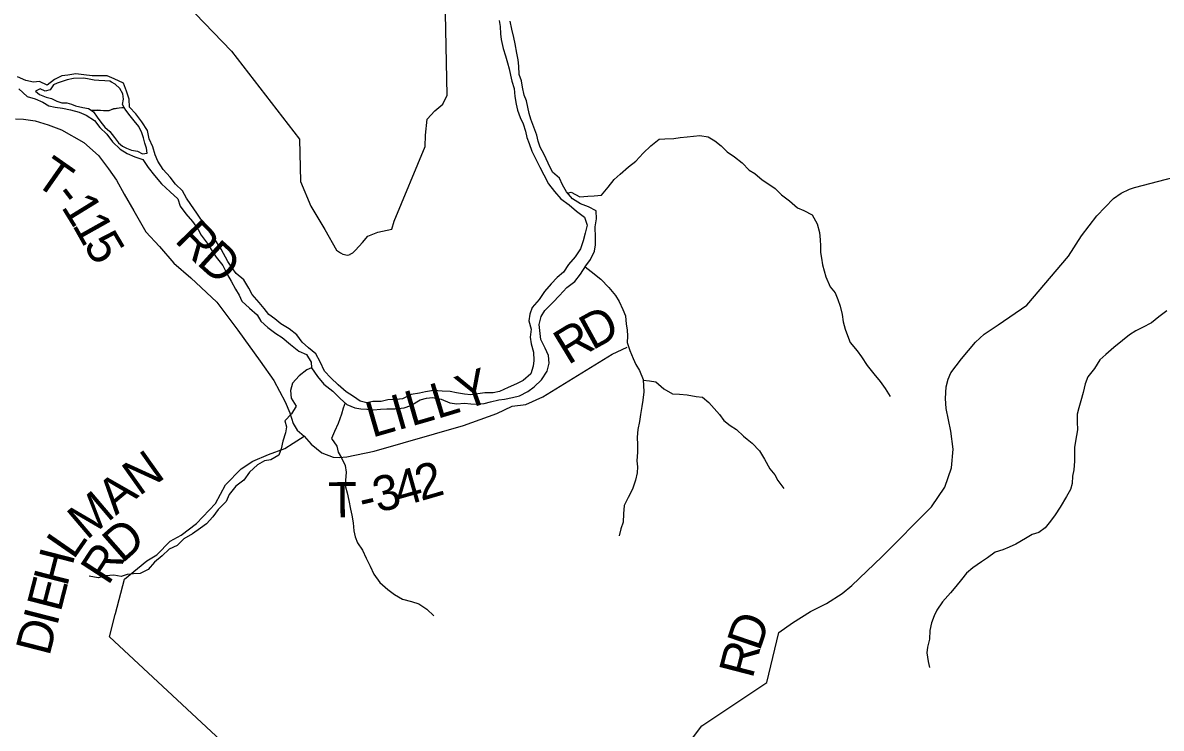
# Model space of a CAD drawing. Extents: x 1624196 to 2029251, y 146837 to 440034.
# Drawn here: x 1784289 to 1793997, y 302092 to 308107 of the extents above; entities that cross this region are included whole.
import ezdxf

# ---------------------------------------------------------------- set-up
doc = ezdxf.new("R2010")
doc.units = 0
for name, color, linetype in [('GM_X_County_Road', 7, 'Continuous'), ('GM_X_County_Road_Text', 7, 'Continuous'), ('GM_X_Minor_Lake', 7, 'Continuous'), ('GM_X_Minor_River', 7, 'Continuous'), ('GM_X_Township_Road', 7, 'Continuous'), ('GM_X_Township_Road_Text', 7, 'Continuous')]:
    doc.layers.add(name, color=color, linetype=linetype)

msp = doc.modelspace()

# ---------------------------------------------------------------- linework, layer by layer
at = {"layer": 'GM_X_County_Road'}
msp.add_lwpolyline([(1788583.9, 300127.8), (1790079.3, 302113.6), (1790633, 302481.1), (1790737.1, 302906.8), (1790852.9, 302990.4), (1791006.8, 303086.3), (1791142.9, 303154), (1791274.8, 303241.7), (1791358.6, 303308.8), (1791613.6, 303554.5), (1792037.8, 303980.6), (1792150.8, 304148.4), (1792209.5, 304311.7), (1792222, 304472.6), (1792202.5, 304625), (1792162.4, 304817.4), (1792156, 304902.5), (1792162.3, 305002.2), (1792180.9, 305067.6), (1792203.7, 305121.2), (1792293, 305242.6), (1792412.3, 305384.4), (1792486.3, 305450.9), (1792605.9, 305531), (1792849.6, 305698.2), (1793205.5, 306117.6), (1793316.5, 306289.4), (1793447.5, 306461.5), (1793590.9, 306607.6), (1793654.6, 306655.1), (1793726.3, 306689.4), (1793768.9, 306703.8), (1794314.5, 306843.9)], dxfattribs=at)
at = {"layer": 'GM_X_Minor_Lake'}
for points in [[(1785046.2, 307600.2), (1785032, 307608.1), (1784990.1, 307612.5), (1784938.1, 307614.9), (1784898.2, 307617.3), (1784856.2, 307625.6), (1784808.4, 307636), (1784720.4, 307632.8), (1784668.3, 307621.2), (1784624.2, 307605.5), (1784582.1, 307591.8), (1784552, 307578.1), (1784523.7, 307536.2), (1784479.6, 307524.6), (1784437.7, 307543), (1784397.6, 307523.2), (1784432.3, 307494.3)], [(1785153.3, 307385.4), (1785138.3, 307410.9), (1785146.7, 307454.9), (1785141.1, 307501.1), (1785115.4, 307545.3), (1785075.8, 307583.7), (1785046.2, 307600.2)], [(1784432.3, 307494.3), (1784489.1, 307472.4), (1784535, 307462), (1784580.8, 307437.6), (1784622.7, 307425.2), (1784664.6, 307424.9), (1784704.5, 307412.5), (1784738.4, 307400.2), (1784800.2, 307385.7), (1784848.2, 307377.3), (1784872.3, 307360.5)], [(1784872.3, 307360.5), (1784928, 307362.6), (1784977.9, 307358.2), (1785021.9, 307357.8), (1785062, 307373.5), (1785110.1, 307381.1), (1785153.3, 307385.4)], [(1784874.1, 307359.3), (1784891.9, 307346.9), (1784923.5, 307302.5), (1784955.1, 307260.2), (1784988.7, 307217.9), (1785030.4, 307179.5), (1785072, 307129), (1785105.6, 307082.7), (1785139.3, 307056.3), (1785173.1, 307038), (1785217, 307019.6), (1785266.9, 307011.2), (1785310.7, 306990.8), (1785350.7, 306994.5), (1785343.1, 307036.6), (1785329.4, 307080.8), (1785319.8, 307125), (1785304.2, 307169.2), (1785278.6, 307221.5), (1785239.1, 307269.9), (1785203.4, 307312.2), (1785167.9, 307360.6), (1785154.5, 307383.4)], [(1785154.5, 307383.4), (1785110.3, 307379.5), (1785062.5, 307371.9), (1785022.2, 307356.1), (1784977.9, 307356.5), (1784927.9, 307360.9), (1784874.1, 307359.3)]]:
    msp.add_lwpolyline(points, dxfattribs=at)
at = {"layer": 'GM_X_Minor_River'}
for points in [[(1788350.8, 308127.5), (1788360.4, 308075.4), (1788361.8, 308013.2), (1788367.4, 307963.1), (1788384.8, 307888.8), (1788406.2, 307824.6), (1788423.7, 307766.3), (1788435.3, 307714.1), (1788448.8, 307659.9), (1788460.4, 307607.8), (1788477.9, 307547.5), (1788485.3, 307479.3), (1788496.7, 307413.1), (1788506.3, 307363), (1788531.8, 307298.7), (1788555.3, 307244.4)], [(1788770.9, 305269.5), (1788743.3, 305333.9), (1788707.8, 305406.3), (1788702.1, 305456.5), (1788692.6, 305534.8), (1788709.1, 305602.9), (1788741.5, 305654.8), (1788808, 305720.6), (1788864.5, 305782.4), (1788927, 305850.2), (1788997.4, 305901.8), (1789043.9, 305963.7), (1789090.4, 306035.6), (1789130.8, 306087.5), (1789163.3, 306159.5), (1789173.7, 306213.6), (1789174.1, 306275.8), (1789168.7, 306366.1), (1789181.2, 306434.2), (1789177.6, 306502.4), (1789113.8, 306536.9), (1789045.9, 306563.4), (1788976.1, 306606), (1788924.5, 306664.5), (1788892.8, 306724.8), (1788865.2, 306781.2), (1788807.5, 306833.7), (1788767.9, 306910.2), (1788734.4, 306982.6), (1788700.8, 307047), (1788685.1, 307097.2), (1788671.4, 307149.5), (1788647.9, 307217.8), (1788620.3, 307284.2), (1788606.6, 307334.4), (1788594.9, 307388.6), (1788585.3, 307440.8), (1788563.6, 307491.1), (1788550, 307559.4), (1788542.4, 307611.6), (1788522.7, 307665.9), (1788519.2, 307736.1), (1788513.5, 307792.3), (1788501.9, 307848.5), (1788488.4, 307928.8), (1788476.8, 307981), (1788459.2, 308051.4), (1788445.7, 308119.6)], [(1785173.2, 307522.8), (1785147.8, 307591.2), (1785068.2, 307629.9), (1785008.4, 307654.4), (1784936.5, 307655), (1784880.5, 307653.5), (1784810.6, 307662.1), (1784740.7, 307672.7), (1784672.6, 307661.2), (1784622.6, 307653.6), (1784560.4, 307624.1), (1784496, 307574.5), (1784432.3, 307605.1), (1784380.2, 307599.5), (1784314.4, 307614.1), (1784244.7, 307644.7)], [(1784255.3, 307542.9), (1784326.9, 307478.3), (1784394.8, 307457.8), (1784458.7, 307429.3), (1784510.6, 307398.8), (1784564.5, 307386.5), (1784626.6, 307378.1), (1784696.5, 307363.6), (1784768.5, 307345), (1784830.4, 307320.6), (1784900.2, 307274), (1784945.8, 307213.5), (1785005.5, 307157), (1785055.1, 307090.5), (1785118.8, 307029.9), (1785178.6, 306993.4), (1785244.5, 306964.9), (1785312.4, 306940.4), (1785358, 306871.9), (1785411.6, 306805.4), (1785473.2, 306732.8), (1785546.8, 306666.1), (1785610.5, 306605.6), (1785632.1, 306543.2), (1785679.7, 306478.8), (1785735.3, 306412.2), (1785784.9, 306345.7), (1785810.6, 306295.4), (1785862.2, 306228.9), (1785901.8, 306164.5), (1785937.5, 306108.1), (1785995.1, 306037.5), (1786034.6, 305957), (1786066.2, 305902.7), (1786101.8, 305836.2), (1786133.5, 305783.9), (1786157.2, 305733.6), (1786222.9, 305673), (1786288.6, 305616.4), (1786320.3, 305564.1), (1786378, 305509.6), (1786447.7, 305457), (1786499.5, 305422.5), (1786571.2, 305363.9), (1786642.9, 305307.3), (1786708.8, 305278.8), (1786748.4, 305214.3), (1786752.1, 305164.2), (1786801.6, 305089.7), (1786857.2, 305025.1), (1786932.9, 304966.5), (1786996.6, 304903.9), (1787052.3, 304853.4), (1787120.2, 304822.9), (1787172.2, 304816.5), (1787222.2, 304812.2), (1787280.2, 304807.8), (1787338.3, 304813.4), (1787394.4, 304815.1), (1787464.5, 304816.6), (1787542.6, 304824.2), (1787598.8, 304843.9), (1787677.2, 304891.5), (1787731.4, 304905.2), (1787781.5, 304910.9), (1787857.5, 304898.3), (1787929.3, 304865.8), (1787991.3, 304857.4), (1788055.4, 304863), (1788109.5, 304858.6), (1788159.5, 304856.3), (1788223.6, 304859.9), (1788277.8, 304875.6), (1788348, 304893.2), (1788398.1, 304898.9), (1788464.2, 304912.5), (1788524.4, 304926.2), (1788596.7, 304963.8), (1788651, 305001.5), (1788711.5, 305063.3), (1788760, 305137.2), (1788776.5, 305203.3), (1788770.9, 305269.5)], [(1788555.3, 307244.4), (1788574.8, 307182.1), (1788588.3, 307127.9), (1788605.9, 307077.7), (1788631.3, 307013.4), (1788698.1, 306876.6), (1788731.5, 306810.2), (1788772.9, 306733.7), (1788824.3, 306669.2), (1788877.8, 306606.7), (1788947.3, 306554), (1789010.8, 306501.4), (1789078.4, 306450.8), (1789101.8, 306382.4), (1789085.2, 306312.5), (1789066.6, 306246.5), (1789046.1, 306180.6), (1788999.5, 306110.8), (1788943, 306045.2), (1788900.5, 305979.5), (1788846.1, 305935.8), (1788793.7, 305882.2), (1788737.2, 305816.5), (1788692.6, 305748.8), (1788634.1, 305679.2), (1788613.6, 305623.2), (1788605.1, 305565.2), (1788624.5, 305494.9), (1788616, 305426.9), (1788625.5, 305370.7), (1788644.9, 305298.5), (1788648.3, 305228.3), (1788641.8, 305178.3), (1788621.3, 305112.3), (1788554.9, 305056.8), (1788498.7, 305029.2), (1788428.4, 304995.8), (1788354.2, 304964.3), (1788300.1, 304952.7), (1788228.1, 304951.3), (1788168.1, 304943.8), (1788110, 304934.3), (1788056.1, 304940.7), (1787986.2, 304951.3), (1787934.4, 304961.8), (1787864.4, 304966.4), (1787792.5, 304971), (1787724.4, 304959.5), (1787672.4, 304947.9), (1787602.3, 304936.5), (1787528, 304901), (1787476, 304893.5), (1787402, 304892.1), (1787345.9, 304876.5), (1787274, 304877.1), (1787221.9, 304865.5), (1787166.1, 304882), (1787110.4, 304920.5), (1787046.8, 304959.1), (1786977.3, 305019.8), (1786915.8, 305078.4), (1786862.3, 305136.9), (1786825, 305215.4), (1786787.6, 305283.8), (1786726.1, 305334.4), (1786670.5, 305382.9), (1786627.1, 305447.4), (1786559.5, 305498), (1786489.9, 305538.7), (1786438.3, 305583.2), (1786386.6, 305619.7), (1786347.1, 305670.1), (1786305.5, 305720.5), (1786246.1, 305791.1), (1786216.6, 305843.4), (1786175.2, 305913.9), (1786107.7, 305970.5), (1786072.2, 306020.9), (1786038.6, 306071.3), (1785979.5, 306175.9), (1785934.1, 306246.4), (1785890.7, 306312.9), (1785867.2, 306369.2), (1785807.8, 306433.8), (1785772.2, 306484.2), (1785720.9, 306558.7), (1785685.3, 306611.1), (1785651.9, 306673.5), (1785590.4, 306730.1), (1785546.9, 306790.5), (1785487.5, 306857.1), (1785442.1, 306925.6), (1785418.5, 306979.9), (1785399.1, 307048.2), (1785367.7, 307116.6), (1785352.3, 307188.8), (1785305, 307261.3), (1785253.6, 307331.9), (1785198.1, 307388.4), (1785196.6, 307454.5), (1785173.2, 307522.8)], [(1788932.7, 306655.1), (1788966.5, 306662.2), (1789040.3, 306621.6), (1789106.4, 306629.2), (1789160.5, 306630.9), (1789222.6, 306638.5), (1789281.1, 306706.3), (1789331.6, 306770.1), (1789384, 306816), (1789454.5, 306879.7), (1789516.8, 306927.4), (1789579.4, 306995.2), (1789643.9, 307059), (1789714.3, 307114.7), (1789764.4, 307116.3), (1789840.5, 307119.9), (1789894.6, 307127.5), (1789954.7, 307135.2), (1790008.8, 307140.8), (1790062.9, 307144.5), (1790132.9, 307134), (1790190.7, 307099.6), (1790244.5, 307059.1), (1790294.2, 307006.6), (1790358, 306964.1), (1790423.7, 306911.5), (1790482, 306849.3)], [(1790482, 306849.3), (1790530.8, 306821), (1790594.7, 306768.4), (1790650.7, 306731.9), (1790704.6, 306693.5), (1790758.4, 306641), (1790828.4, 306588.4), (1790896.2, 306529.8), (1790948.3, 306507.4), (1791020.3, 306468.8), (1791063.9, 306392.3), (1791081.5, 306317.9), (1791089.1, 306255.7), (1791092.8, 306205.5), (1791092.4, 306149.3), (1791100.1, 306099.1), (1791109.8, 306042.8), (1791123.5, 305990.6), (1791137.2, 305940.3), (1791174.8, 305855.8), (1791216.6, 305803.4), (1791238.3, 305747), (1791258, 305690.7), (1791275.6, 305620.4), (1791285.3, 305558.1), (1791302.9, 305493.8), (1791322.6, 305441.5), (1791344.3, 305381.2), (1791404.1, 305308.6), (1791441.9, 305258.1), (1791489.6, 305185.6), (1791547.3, 305113), (1791599.1, 305048.5), (1791642.8, 304988), (1791684.5, 304919.5)], [(1789083.4, 306024.8), (1789136.1, 305987.2), (1789217.8, 305920.5), (1789285.4, 305849.9), (1789343, 305781.3), (1789374.7, 305731), (1789406.3, 305662.5), (1789427.9, 305608.3), (1789435.5, 305538), (1789443.1, 305487.8), (1789444.8, 305435.7), (1789442.4, 305381.5), (1789466, 305313.2), (1789493.6, 305244.8), (1789517.2, 305192.5), (1789548.9, 305142.2), (1789578.5, 305065.8), (1789585.8, 304961.4), (1789577.3, 304889.3), (1789566.9, 304835.2), (1789556.4, 304767.1), (1789548, 304707), (1789533.6, 304638.9), (1789529.1, 304574.7), (1789530.7, 304508.5), (1789532.2, 304446.3), (1789525.7, 304372.2), (1789531.4, 304320), (1789529.1, 304269.9), (1789512.6, 304207.8), (1789488.1, 304129.7), (1789451.6, 304059.8), (1789417.1, 303991.8), (1789412.6, 303919.6), (1789410.1, 303847.5), (1789389.7, 303793.4), (1789375.3, 303731.4)], [(1794043.7, 305652), (1793975.1, 305600.2), (1793914.6, 305548.4), (1793836, 305508.7), (1793781.7, 305480.9), (1793725.2, 305445.1), (1793666.7, 305397.3), (1793592.1, 305339.6), (1793525.4, 305277.8), (1793472.9, 305231.9), (1793428.3, 305160), (1793371.6, 305088), (1793349.2, 305028), (1793330.6, 304953.8), (1793310.1, 304883.7), (1793293.6, 304823.6), (1793281.2, 304769.5), (1793278.8, 304705.3), (1793282.4, 304637), (1793265.7, 304540.8), (1793257.3, 304484.7), (1793256.9, 304430.5), (1793258.5, 304370.3), (1793252, 304296.1), (1793241.6, 304239.9), (1793237.2, 304177.7), (1793222.8, 304127.7), (1793190.3, 304067.6), (1793135.5, 303977.7), (1793093, 303911.7), (1793052.5, 303857.8), (1793005.9, 303799.8), (1792953.5, 303760), (1792895.1, 303742.3), (1792838.7, 303710.5), (1792756.1, 303660.9), (1792699.7, 303635.1), (1792645.4, 303613.4), (1792581, 303591.7), (1792516.5, 303545.9), (1792464.1, 303510.1), (1792391.5, 303460.4), (1792337, 303414.5), (1792294.5, 303358.6), (1792245.9, 303300.7), (1792199.4, 303246.8), (1792132.7, 303168.9), (1792084, 303099), (1792061.6, 303048.9), (1792037.2, 302990.9), (1792024.7, 302924.7), (1792022.2, 302852.5), (1792003.7, 302784.4), (1791999.3, 302734.2), (1792008.9, 302659.9), (1792020.6, 302609.7)], [(1786752.1, 305164.2), (1786711.9, 305148.4), (1786645.5, 305096.7), (1786589, 305034.9), (1786570.6, 304970.8), (1786578.1, 304906.6), (1786619.7, 304838.1), (1786579.2, 304772.2), (1786522.8, 304712.4), (1786538.4, 304662.1), (1786530.1, 304610.1), (1786505.6, 304540), (1786491.1, 304473.9), (1786472.8, 304419.9), (1786404.4, 304380.2), (1786350.3, 304372.5), (1786290, 304336.8), (1786223.5, 304275.1), (1786173, 304207.2), (1786106.6, 304155.5), (1786050, 304085.7), (1786023.6, 304025.7), (1785955.1, 303955.9), (1785910.6, 303894), (1785856.1, 303834.2), (1785805.9, 303798.5), (1785735.5, 303748.8), (1785663.1, 303707.1), (1785604.6, 303649.3), (1785538.4, 303617.6), (1785477.9, 303561.9), (1785413.5, 303508.1), (1785359, 303444.3), (1785290.7, 303410.7), (1785232.6, 303407), (1785178.5, 303401.4), (1785128.3, 303385.6), (1785066.3, 303396.1), (1784996.2, 303390.5), (1784932.1, 303374.9), (1784856.1, 303387.4)], [(1789578.9, 305059.2), (1789634.4, 305053.4), (1789686.4, 305045), (1789756.1, 304986.4), (1789829.9, 304943.8), (1789888, 304941.5), (1789954, 304935), (1790030, 304920.5), (1790084, 304914.1), (1790139.7, 304869.6), (1790183.4, 304817.2), (1790229.2, 304766.8), (1790266.9, 304716.4), (1790320.6, 304673.9), (1790376.5, 304639.5), (1790434.1, 304580.9), (1790466.2, 304555.6)], [(1787037.4, 304866.9), (1787022, 304821.5), (1787007.7, 304769.4), (1786977.1, 304691.4), (1786946.6, 304621.4), (1786922.2, 304563.4), (1786967.8, 304496.9), (1786979.5, 304446.7), (1787007.2, 304396.4), (1787038.8, 304332), (1787046.4, 304273.8), (1787039.9, 304203.7), (1787041.6, 304151.5), (1787055.2, 304099.3), (1787068.8, 304035), (1787084.3, 303958.7), (1787094, 303908.5), (1787107.6, 303844.2), (1787113.1, 303774), (1787122.8, 303723.8), (1787144.5, 303671.5), (1787186.1, 303609.1), (1787217.7, 303542.7), (1787251.3, 303474.3), (1787282.8, 303405.9), (1787334.4, 303335.3), (1787402.1, 303274.8), (1787457.9, 303232.3), (1787525.7, 303193.7), (1787603.6, 303173.2), (1787667.6, 303152.7), (1787735.3, 303106.1), (1787793, 303049.6)], [(1790466.2, 304555.6), (1790507.7, 304523.2), (1790571.5, 304456.6), (1790613.2, 304386.1), (1790658.8, 304303.6), (1790700.6, 304253.2), (1790728.4, 304202.8), (1790778.2, 304136.3)]]:
    msp.add_lwpolyline(points, dxfattribs=at)
at = {"layer": 'GM_X_Township_Road'}
for points in [[(1785681.2, 308266.2), (1786069.6, 307865.3), (1786647.8, 307116), (1786656.9, 306753.1), (1786744.4, 306542.3), (1786863.9, 306343.5), (1786965.5, 306168.8), (1786997.2, 306144.1), (1787019.2, 306134.7), (1787057.4, 306124.5), (1787081.9, 306131.5), (1787081.9, 306134.7), (1787103.9, 306144.1), (1787127.5, 306168.4), (1787185.6, 306234.5), (1787231.8, 306288.5), (1787317.8, 306320.4), (1787435, 306346.6), (1787456.1, 306414.2), (1787721.6, 307051.2), (1787721.9, 307149.5), (1787738.2, 307285.7), (1787802.4, 307355.8), (1787870.5, 307411.7), (1787908.7, 307489.8), (1787889, 308466.3)], [(1784226.2, 307288.4), (1784294.1, 307284.2), (1784396.1, 307271.9), (1784506, 307235.6), (1784617.9, 307193.2), (1784809.7, 307086.5), (1784935.4, 306975.9), (1785019.1, 306861.4), (1785088.9, 306765), (1785154.6, 306646.5), (1785236.3, 306503.9), (1785337.8, 306325.2), (1785455.5, 306198.6), (1785577.2, 306058), (1785720.9, 305931.3), (1785942.4, 305724.3), (1786123.8, 305485.2), (1786313.2, 305222.1), (1786428.8, 305057.4), (1786526.3, 304874.7), (1786566.1, 304780.4), (1786595.9, 304690.1), (1786627.8, 304631.9), (1786687.9, 304582.3)], [(1786687.9, 304582.3), (1786749.5, 304513.3), (1786839.3, 304440.9), (1786935.2, 304404.5), (1786987.5, 304399.3), (1787053.2, 304406.2), (1787285.3, 304453.8), (1788047.9, 304672.5), (1788330.1, 304776), (1788462.3, 304837.9), (1788578.3, 304851.6), (1788722.5, 304917.4), (1789131.1, 305169), (1789315.4, 305280.9), (1789441.5, 305340.7)], [(1785077.1, 303060.2), (1785079.4, 303068.8), (1785156.6, 303362.4), (1785347, 303518.3), (1785431.1, 303570.2), (1785545.4, 303686.2), (1785639.6, 303738.1), (1785769.8, 303838), (1785932.2, 304008), (1786018.6, 304168.2), (1786150.9, 304304.2), (1786251.1, 304368.1), (1786385.2, 304425.9), (1786523.4, 304477.7), (1786593.5, 304521.7), (1786687.9, 304582.3)], [(1785483.6, 299989.1), (1785707.5, 300474), (1786308.5, 301679.4), (1785027.4, 302871.4), (1785077.1, 303060.2)]]:
    msp.add_lwpolyline(points, dxfattribs=at)

# ---------------------------------------------------------------- texts
at = {"layer": 'GM_X_County_Road_Text'}
for s, rotation, p in [('D', 71.15263, (1790571.8, 302740.6)), ('R', 75.51885, (1790511.9, 302507.8))]:
    msp.add_text(s, height=300, rotation=rotation, dxfattribs=at).set_placement(p)
at = {"layer": 'GM_X_Township_Road_Text'}
for s, rotation, p in [('T', 325.02378, (1784375.3, 306740.4)), ('-', 307.44913, (1784541.7, 306628.5)), ('1', 301.65013, (1784612, 306537.3)), ('1', 299.32856, (1784707.3, 306382.7)), ('R', 313.97604, (1785576.1, 306246.8)), ('5', 300.64159, (1784801.6, 306215.1)), ('D', 317.90193, (1785763.1, 306054.1)), ('D', 28.76977, (1789145.9, 305311.2)), ('R', 31.29709, (1788938.4, 305185)), ('Y', 20.06405, (1788053.8, 304798.7)), ('L', 16.83863, (1787821.8, 304727.9)), ('I', 16.07192, (1787483.7, 304630.3)), ('L', 16.10427, (1787602.2, 304664.5)), ('L', 16.0802, (1787268.1, 304568.2)), ('N', 35.36236, (1785280.5, 304067)), ('2', 16.26247, (1787685, 304028.2)), ('3', 14.32751, (1787317.5, 303929)), ('4', 15.89845, (1787505.3, 303977)), ('A', 39.92404, (1785083, 303901.5)), ('T', 0.45856, (1786894.8, 303889.3)), ('M', 40.29151, (1784835, 303691.2)), ('-', 12.99324, (1787190.1, 303899.5)), ('D', 41.26234, (1785136.5, 303492.3)), ('L', 55.3043, (1784721.2, 303522.1)), ('H', 75.61404, (1784667.2, 303291.8)), ('R', 56.98758, (1785016.5, 303302.1)), ('E', 75.61243, (1784611.5, 303074.4)), ('I', 75.61388, (1784580.9, 302955.1)), ('D', 75.61299, (1784515.3, 302699.4))]:
    msp.add_text(s, height=300, rotation=rotation, dxfattribs=at).set_placement(p)

doc.saveas('drawing.dxf')
